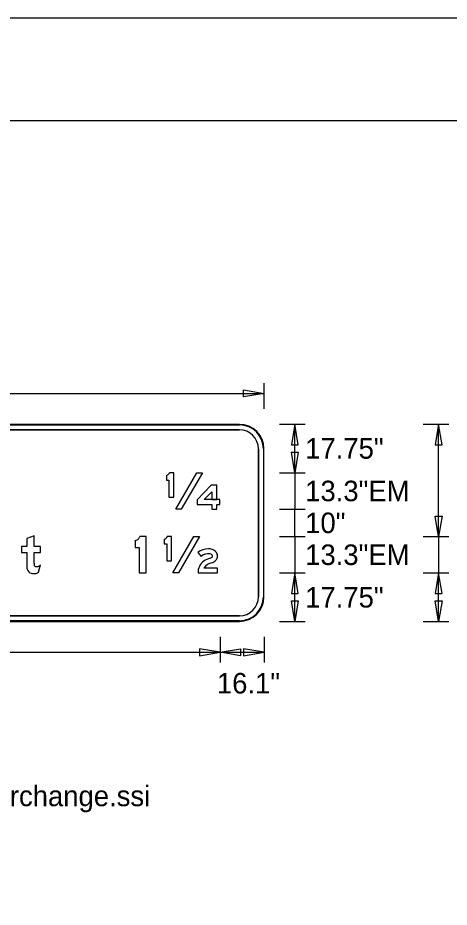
# Model space of a CAD drawing. Extents: x 1806251 to 1809821, y 414895 to 422886.
# Drawn here: x 1809677.776 to 1809679.352, y 414950.976 to 414954.226 of the extents above; entities that cross this region are included whole.
import ezdxf

# ---------------------------------------------------------------- set-up
doc = ezdxf.new("R2010")
doc.units = 0
for name, color, linetype in [('GSBWFILL', 7, 'Continuous'), ('GSCOLORFILL', 7, 'Continuous'), ('GSDIMS', 7, 'Continuous'), ('GSOUTLINE', 7, 'Continuous'), ('GSSHT', 7, 'Continuous')]:
    doc.layers.add(name, color=color, linetype=linetype)

msp = doc.modelspace()

# ---------------------------------------------------------------- linework, layer by layer
at = {"layer": 'GSBWFILL'}
for p, q in [((1809678.5855, 414952.7405), (1809676.6055, 414952.7405)), ((1809676.6055, 414952.7205), (1809678.5855, 414952.7205)), ((1809678.6555, 414952.6505), (1809678.6555, 414952.1105)), ((1809678.6755, 414952.1105), (1809678.6755, 414952.6505)), ((1809678.4342, 414952.2717), (1809678.4458, 414952.2581)), ((1809677.8523, 414952.2), (1809677.8593, 414952.2275)), ((1809678.5855, 414952.0405), (1809676.6057, 414952.0405)), ((1809676.6057, 414952.0205), (1809678.5855, 414952.0205))]:
    msp.add_line(p, q, dxfattribs=at)
for points in [[(1809678.3194, 414952.5536), (1809678.3194, 414952.5367), (1809678.3285, 414952.5367), (1809678.3285, 414952.4748), (1809678.346, 414952.4748), (1809678.346, 414952.5635), (1809678.3306, 414952.5635)], [(1809677.8354, 414952.2327), (1809677.8354, 414952.2716), (1809677.8593, 414952.2716), (1809677.8593, 414952.2946), (1809677.8354, 414952.2946), (1809677.8354, 414952.3328), (1809677.8088, 414952.3227), (1809677.8088, 414952.2946), (1809677.7902, 414952.2946), (1809677.7902, 414952.2716), (1809677.8088, 414952.2716), (1809677.8088, 414952.2247)], [(1809678.2053, 414952.3157), (1809678.2053, 414952.2903), (1809678.219, 414952.2903), (1809678.219, 414952.1975), (1809678.2452, 414952.1975), (1809678.2452, 414952.3305), (1809678.2221, 414952.3305)], [(1809678.3112, 414952.3206), (1809678.3112, 414952.3037), (1809678.3203, 414952.3037), (1809678.3203, 414952.2418), (1809678.3378, 414952.2418), (1809678.3378, 414952.3305), (1809678.3224, 414952.3305)], [(1809678.4345, 414952.1975), (1809678.506, 414952.1975), (1809678.506, 414952.215), (1809678.4562, 414952.215)]]:
    msp.add_lwpolyline(points, dxfattribs=at)
for points in [[(1809678.4299, 414952.5635), (1809678.4504, 414952.5635), (1809678.3736, 414952.4305), (1809678.3531, 414952.4305)], [(1809678.4847, 414952.4305), (1809678.5029, 414952.4305), (1809678.5029, 414952.4479), (1809678.5142, 414952.4479), (1809678.5142, 414952.4658), (1809678.4569, 414952.4658), (1809678.4569, 414952.4658), (1809678.4847, 414952.4943), (1809678.4847, 414952.4658), (1809678.5029, 414952.4658), (1809678.5029, 414952.5179), (1809678.4847, 414952.5179), (1809678.4826, 414952.5179), (1809678.4826, 414952.5179), (1809678.4313, 414952.465), (1809678.4313, 414952.4479), (1809678.4847, 414952.4479)], [(1809678.4193, 414952.3305), (1809678.4398, 414952.3305), (1809678.3631, 414952.1975), (1809678.3426, 414952.1975)]]:
    msp.add_lwpolyline(points, close=True, dxfattribs=at)
for centre, radius, start, end in [((1809678.5855, 414952.6505), 0.09, 0, 90), ((1809678.5855, 414952.6505), 0.07, 0, 90), ((1809678.3158, 414952.5691), 0.0158, 316.0835, 327.7887), ((1809678.3158, 414952.5691), 0.0158, 327.7887, 339.494), ((1809678.3158, 414952.5691), 0.0158, 283.2584, 299.6709), ((1809678.3158, 414952.5691), 0.0158, 299.6709, 316.0835), ((1809677.8604, 414952.2247), 0.0516, 180, 194.8913), ((1809677.8314, 414952.217), 0.0216, 194.8913, 254.4117), ((1809678.0019, 414952.2327), 0.1665, 180, 182.0173), ((1809677.843, 414952.2282), 0.00765, 189.7434, 227.9584), ((1809677.8433, 414952.2284), 0.00801, 227.9584, 270), ((1809677.8433, 414952.2624), 0.042, 270, 279.6927), ((1809677.8486, 414952.2309), 0.00997, 279.6927, 305.2189), ((1809677.8418, 414952.2406), 0.0218, 305.2189, 323.2877), ((1809677.8354, 414952.2313), 0.0364, 254.4117, 270), ((1809677.8354, 414952.2473), 0.0525, 270, 273.675), ((1809677.8373, 414952.2165), 0.0216, 273.675, 286.3959), ((1809677.8345, 414952.2261), 0.0316, 286.3959, 304.22), ((1809678.5855, 414952.1105), 0.09, 270, 0), ((1809678.5855, 414952.1105), 0.07, 270, 0)]:
    msp.add_arc(centre, radius, start, end, dxfattribs=at)
for centre, major_axis, ratio, start_param, end_param in [((1809678.1999, 414952.3388), (0, 0.0238), 0.999985, 3.372996, 3.659448), ((1809678.1999, 414952.3388), (0, 0.0238), 0.999985, 3.659448, 3.945901), ((1809678.1999, 414952.3388), (0, 0.0238), 0.999985, 3.945901, 4.150196), ((1809678.1999, 414952.3388), (0, 0.0238), 0.999985, 4.150196, 4.354491), ((1809678.3076, 414952.3361), (0, 0.0158), 0.999478, 3.372996, 3.659448), ((1809678.3076, 414952.3361), (0, 0.0158), 0.999478, 3.659448, 3.945901), ((1809678.3076, 414952.3361), (0, 0.0158), 0.999478, 3.945901, 4.150196), ((1809678.3076, 414952.3361), (0, 0.0158), 0.999478, 4.150196, 4.354491), ((1809678.4707, 414952.23), (0, 0.0555), 0.999478, 6.248407, 7.003021), ((1809678.4709, 414952.2304), (0, 0.0374), 0.999478, 6.094132, 7.020883), ((1809678.4741, 414952.2489), (0, 0.0366), 0.999478, 5.550079, 6.322931), ((1809678.4756, 414952.2517), (0, 0.0156), 0.999478, 5.490532, 6.129979), ((1809678.4815, 414952.2582), (0, 0.0247), 0.999478, 4.806893, 5.518533), ((1809678.4851, 414952.1993), (0, 0.0506), 0.999478, 0.626572, 1.605438), ((1809678.495, 414952.1855), (0, 0.0676), 0.999478, 0.230695, 0.626088), ((1809678.4928, 414952.1917), (0, 0.0434), 0.999478, 0.176082, 1.00426), ((1809678.4761, 414952.2641), (0, 0.0132), 0.999478, 3.400739, 4.168985), ((1809678.4762, 414952.264), (0, 0.0309), 0.999478, 3.438365, 3.951913), ((1809678.4838, 414952.2595), (0, 0.0043), 0.999478, 4.157725, 5.534803), ((1809678.4816, 414952.2603), (0, 0.0244), 0.999478, 3.907466, 4.724085)]:
    msp.add_ellipse(centre, major_axis=major_axis, ratio=ratio, start_param=start_param, end_param=end_param, dxfattribs=at)
at = {"layer": 'GSCOLORFILL'}
for p, q in [((1809678.5855, 414952.7405), (1809676.6055, 414952.7405)), ((1809678.5855, 414952.7405), (1809676.6055, 414952.7405)), ((1809678.5855, 414952.7405), (1809676.6055, 414952.7405)), ((1809676.6055, 414952.7385), (1809678.5855, 414952.7385)), ((1809676.6055, 414952.7205), (1809678.5855, 414952.7205)), ((1809678.6555, 414952.6505), (1809678.6555, 414952.1105)), ((1809678.6735, 414952.6505), (1809678.6735, 414952.1105)), ((1809678.6755, 414952.1105), (1809678.6755, 414952.6505)), ((1809678.6755, 414952.1105), (1809678.6755, 414952.6505)), ((1809678.6755, 414952.1105), (1809678.6755, 414952.6505)), ((1809678.4342, 414952.2717), (1809678.4458, 414952.2581)), ((1809677.8523, 414952.2), (1809677.8593, 414952.2275)), ((1809678.5855, 414952.0405), (1809676.6057, 414952.0405)), ((1809678.5855, 414952.0225), (1809676.6055, 414952.0225)), ((1809676.6055, 414952.0205), (1809678.5855, 414952.0205)), ((1809676.6055, 414952.0205), (1809678.5855, 414952.0205)), ((1809676.6057, 414952.0205), (1809678.5855, 414952.0205))]:
    msp.add_line(p, q, dxfattribs=at)
for points in [[(1809678.3194, 414952.5536), (1809678.3194, 414952.5367), (1809678.3285, 414952.5367), (1809678.3285, 414952.4748), (1809678.346, 414952.4748), (1809678.346, 414952.5635), (1809678.3306, 414952.5635)], [(1809677.8354, 414952.2327), (1809677.8354, 414952.2716), (1809677.8593, 414952.2716), (1809677.8593, 414952.2946), (1809677.8354, 414952.2946), (1809677.8354, 414952.3328), (1809677.8088, 414952.3227), (1809677.8088, 414952.2946), (1809677.7902, 414952.2946), (1809677.7902, 414952.2716), (1809677.8088, 414952.2716), (1809677.8088, 414952.2247)], [(1809678.2053, 414952.3157), (1809678.2053, 414952.2903), (1809678.219, 414952.2903), (1809678.219, 414952.1975), (1809678.2452, 414952.1975), (1809678.2452, 414952.3305), (1809678.2221, 414952.3305)], [(1809678.3112, 414952.3206), (1809678.3112, 414952.3037), (1809678.3203, 414952.3037), (1809678.3203, 414952.2418), (1809678.3378, 414952.2418), (1809678.3378, 414952.3305), (1809678.3224, 414952.3305)], [(1809678.4345, 414952.1975), (1809678.506, 414952.1975), (1809678.506, 414952.215), (1809678.4562, 414952.215)]]:
    msp.add_lwpolyline(points, dxfattribs=at)
for points in [[(1809678.4299, 414952.5635), (1809678.4504, 414952.5635), (1809678.3736, 414952.4305), (1809678.3531, 414952.4305)], [(1809678.4847, 414952.4305), (1809678.5029, 414952.4305), (1809678.5029, 414952.4479), (1809678.5142, 414952.4479), (1809678.5142, 414952.4658), (1809678.4569, 414952.4658), (1809678.4569, 414952.4658), (1809678.4847, 414952.4943), (1809678.4847, 414952.4658), (1809678.5029, 414952.4658), (1809678.5029, 414952.5179), (1809678.4847, 414952.5179), (1809678.4826, 414952.5179), (1809678.4826, 414952.5179), (1809678.4313, 414952.465), (1809678.4313, 414952.4479), (1809678.4847, 414952.4479)], [(1809678.4193, 414952.3305), (1809678.4398, 414952.3305), (1809678.3631, 414952.1975), (1809678.3426, 414952.1975)]]:
    msp.add_lwpolyline(points, close=True, dxfattribs=at)
for centre, radius, start, end in [((1809678.5855, 414952.6505), 0.09, 0, 90), ((1809678.5855, 414952.6505), 0.09, 0, 90), ((1809678.5855, 414952.6505), 0.09, 0, 90), ((1809678.5855, 414952.6505), 0.088, 0, 90), ((1809678.5855, 414952.6505), 0.07, 0, 90), ((1809678.3158, 414952.5691), 0.0158, 316.0835, 327.7887), ((1809678.3158, 414952.5691), 0.0158, 327.7887, 339.494), ((1809678.3158, 414952.5691), 0.0158, 283.2584, 299.6709), ((1809678.3158, 414952.5691), 0.0158, 299.6709, 316.0835), ((1809677.8604, 414952.2247), 0.0516, 180, 194.8913), ((1809677.8314, 414952.217), 0.0216, 194.8913, 254.4117), ((1809678.0019, 414952.2327), 0.1665, 180, 182.0173), ((1809677.843, 414952.2282), 0.00765, 189.7434, 227.9584), ((1809677.8433, 414952.2284), 0.00801, 227.9584, 270), ((1809677.8433, 414952.2624), 0.042, 270, 279.6927), ((1809677.8486, 414952.2309), 0.00997, 279.6927, 305.2189), ((1809677.8418, 414952.2406), 0.0218, 305.2189, 323.2877), ((1809677.8354, 414952.2313), 0.0364, 254.4117, 270), ((1809677.8354, 414952.2473), 0.0525, 270, 273.675), ((1809677.8373, 414952.2165), 0.0216, 273.675, 286.3959), ((1809677.8345, 414952.2261), 0.0316, 286.3959, 304.22), ((1809678.5855, 414952.1105), 0.09, 270, 0), ((1809678.5855, 414952.1105), 0.09, 270, 0), ((1809678.5855, 414952.1105), 0.07, 270, 0), ((1809678.5855, 414952.1105), 0.09, 270, 0), ((1809678.5855, 414952.1105), 0.088, 270, 0)]:
    msp.add_arc(centre, radius, start, end, dxfattribs=at)
for centre, major_axis, ratio, start_param, end_param in [((1809678.1999, 414952.3388), (0, 0.0238), 0.999985, 3.372996, 3.659448), ((1809678.1999, 414952.3388), (0, 0.0238), 0.999985, 3.659448, 3.945901), ((1809678.1999, 414952.3388), (0, 0.0238), 0.999985, 3.945901, 4.150196), ((1809678.1999, 414952.3388), (0, 0.0238), 0.999985, 4.150196, 4.354491), ((1809678.3076, 414952.3361), (0, 0.0158), 0.999478, 3.372996, 3.659448), ((1809678.3076, 414952.3361), (0, 0.0158), 0.999478, 3.659448, 3.945901), ((1809678.3076, 414952.3361), (0, 0.0158), 0.999478, 3.945901, 4.150196), ((1809678.3076, 414952.3361), (0, 0.0158), 0.999478, 4.150196, 4.354491), ((1809678.4707, 414952.23), (0, 0.0555), 0.999478, 6.248407, 7.003021), ((1809678.4709, 414952.2304), (0, 0.0374), 0.999478, 6.094132, 7.020883), ((1809678.4741, 414952.2489), (0, 0.0366), 0.999478, 5.550079, 6.322931), ((1809678.4756, 414952.2517), (0, 0.0156), 0.999478, 5.490532, 6.129979), ((1809678.4815, 414952.2582), (0, 0.0247), 0.999478, 4.806893, 5.518533), ((1809678.4851, 414952.1993), (0, 0.0506), 0.999478, 0.626572, 1.605438), ((1809678.495, 414952.1855), (0, 0.0676), 0.999478, 0.230695, 0.626088), ((1809678.4928, 414952.1917), (0, 0.0434), 0.999478, 0.176082, 1.00426), ((1809678.4761, 414952.2641), (0, 0.0132), 0.999478, 3.400739, 4.168985), ((1809678.4762, 414952.264), (0, 0.0309), 0.999478, 3.438365, 3.951913), ((1809678.4838, 414952.2595), (0, 0.0043), 0.999478, 4.157725, 5.534803), ((1809678.4816, 414952.2603), (0, 0.0244), 0.999478, 3.907466, 4.724085)]:
    msp.add_ellipse(centre, major_axis=major_axis, ratio=ratio, start_param=start_param, end_param=end_param, dxfattribs=at)
at = {"layer": 'GSDIMS'}
for p, q in [((1809678.676, 414952.7973), (1809678.676, 414952.891)), ((1809676.515, 414952.8535), (1809678.676, 414952.8535)), ((1809678.7323, 414952.741), (1809678.826, 414952.741)), ((1809678.7885, 414952.5635), (1809678.7885, 414952.741)), ((1809679.2573, 414952.741), (1809679.351, 414952.741)), ((1809679.3135, 414952.3305), (1809679.3135, 414952.741)), ((1809678.7323, 414952.5635), (1809678.826, 414952.5635)), ((1809678.7323, 414952.5635), (1809678.826, 414952.5635)), ((1809678.7885, 414952.5635), (1809678.7885, 414952.4305)), ((1809678.7323, 414952.4305), (1809678.826, 414952.4305)), ((1809678.7323, 414952.4305), (1809678.826, 414952.4305)), ((1809678.7885, 414952.3305), (1809678.7885, 414952.4305)), ((1809678.7323, 414952.3305), (1809678.826, 414952.3305)), ((1809678.7323, 414952.3305), (1809678.826, 414952.3305)), ((1809678.7885, 414952.3305), (1809678.7885, 414952.1975)), ((1809679.2573, 414952.3305), (1809679.351, 414952.3305)), ((1809679.2573, 414952.3305), (1809679.351, 414952.3305)), ((1809679.3135, 414952.3305), (1809679.3135, 414952.1975)), ((1809678.7323, 414952.1975), (1809678.826, 414952.1975)), ((1809678.7323, 414952.1975), (1809678.826, 414952.1975)), ((1809678.7885, 414952.02), (1809678.7885, 414952.1975)), ((1809679.2573, 414952.1975), (1809679.351, 414952.1975)), ((1809679.2573, 414952.1975), (1809679.351, 414952.1975)), ((1809679.3135, 414952.02), (1809679.3135, 414952.1975)), ((1809678.7323, 414952.02), (1809678.826, 414952.02)), ((1809679.2573, 414952.02), (1809679.351, 414952.02)), ((1809678.515, 414951.9637), (1809678.515, 414951.87)), ((1809678.515, 414951.9637), (1809678.515, 414951.87)), ((1809678.676, 414951.9637), (1809678.676, 414951.87)), ((1809676.6764, 414951.9075), (1809678.515, 414951.9075)), ((1809678.515, 414951.9075), (1809678.676, 414951.9075))]:
    msp.add_line(p, q, dxfattribs=at)
for points in [[(1809678.676, 414952.8535), (1809678.601, 414952.841), (1809678.601, 414952.866)], [(1809678.7885, 414952.741), (1809678.776, 414952.666), (1809678.801, 414952.666)], [(1809679.3135, 414952.741), (1809679.301, 414952.666), (1809679.326, 414952.666)], [(1809678.7885, 414952.5635), (1809678.776, 414952.6385), (1809678.801, 414952.6385)], [(1809679.3135, 414952.3305), (1809679.301, 414952.4055), (1809679.326, 414952.4055)], [(1809678.7885, 414952.1975), (1809678.776, 414952.1225), (1809678.801, 414952.1225)], [(1809679.3135, 414952.1975), (1809679.301, 414952.1225), (1809679.326, 414952.1225)], [(1809678.7885, 414952.02), (1809678.776, 414952.095), (1809678.801, 414952.095)], [(1809679.3135, 414952.02), (1809679.301, 414952.095), (1809679.326, 414952.095)], [(1809678.515, 414951.9075), (1809678.44, 414951.92), (1809678.44, 414951.895)], [(1809678.515, 414951.9075), (1809678.59, 414951.92), (1809678.59, 414951.895)], [(1809678.676, 414951.9075), (1809678.601, 414951.92), (1809678.601, 414951.895)]]:
    msp.add_lwpolyline(points, close=True, dxfattribs=at)
at = {"layer": 'GSOUTLINE'}
for p, q in [((1809678.5855, 414952.7405), (1809676.6055, 414952.7405)), ((1809678.5855, 414952.7205), (1809676.6055, 414952.7205)), ((1809678.6555, 414952.1105), (1809678.6555, 414952.6505)), ((1809678.6755, 414952.1105), (1809678.6755, 414952.6505)), ((1809678.4342, 414952.2717), (1809678.4458, 414952.2581)), ((1809677.8523, 414952.2), (1809677.8593, 414952.2275)), ((1809676.6055, 414952.0405), (1809678.5855, 414952.0405)), ((1809676.6055, 414952.0205), (1809678.5855, 414952.0205))]:
    msp.add_line(p, q, dxfattribs=at)
for points in [[(1809678.3194, 414952.5536), (1809678.3194, 414952.5367), (1809678.3285, 414952.5367), (1809678.3285, 414952.4748), (1809678.346, 414952.4748), (1809678.346, 414952.5635), (1809678.3306, 414952.5635)], [(1809677.8354, 414952.2327), (1809677.8354, 414952.2716), (1809677.8593, 414952.2716), (1809677.8593, 414952.2946), (1809677.8354, 414952.2946), (1809677.8354, 414952.3328), (1809677.8088, 414952.3227), (1809677.8088, 414952.2946), (1809677.7902, 414952.2946), (1809677.7902, 414952.2716), (1809677.8088, 414952.2716), (1809677.8088, 414952.2247)], [(1809678.2053, 414952.3157), (1809678.2053, 414952.2903), (1809678.219, 414952.2903), (1809678.219, 414952.1975), (1809678.2452, 414952.1975), (1809678.2452, 414952.3305), (1809678.2221, 414952.3305)], [(1809678.3112, 414952.3206), (1809678.3112, 414952.3037), (1809678.3203, 414952.3037), (1809678.3203, 414952.2418), (1809678.3378, 414952.2418), (1809678.3378, 414952.3305), (1809678.3224, 414952.3305)], [(1809678.4345, 414952.1975), (1809678.506, 414952.1975), (1809678.506, 414952.215), (1809678.4562, 414952.215)]]:
    msp.add_lwpolyline(points, dxfattribs=at)
for points in [[(1809678.4299, 414952.5635), (1809678.4504, 414952.5635), (1809678.3736, 414952.4305), (1809678.3531, 414952.4305)], [(1809678.5029, 414952.4305), (1809678.5029, 414952.4479), (1809678.5142, 414952.4479), (1809678.5142, 414952.4658), (1809678.5029, 414952.4658), (1809678.5029, 414952.5179), (1809678.4847, 414952.5179), (1809678.4826, 414952.5179), (1809678.4826, 414952.5179), (1809678.4313, 414952.465), (1809678.4313, 414952.4479), (1809678.4847, 414952.4479), (1809678.4847, 414952.4305)], [(1809678.4847, 414952.4943), (1809678.4847, 414952.4658), (1809678.4569, 414952.4658)], [(1809678.4193, 414952.3305), (1809678.4398, 414952.3305), (1809678.3631, 414952.1975), (1809678.3426, 414952.1975)]]:
    msp.add_lwpolyline(points, close=True, dxfattribs=at)
for centre, radius, start, end in [((1809678.5855, 414952.6505), 0.09, 0, 90), ((1809678.5855, 414952.6505), 0.07, 0, 90), ((1809678.3158, 414952.5691), 0.0158, 316.0835, 327.7887), ((1809678.3158, 414952.5691), 0.0158, 327.7887, 339.494), ((1809678.3158, 414952.5691), 0.0158, 283.2584, 299.6709), ((1809678.3158, 414952.5691), 0.0158, 299.6709, 316.0835), ((1809677.8604, 414952.2247), 0.0516, 180, 194.8913), ((1809677.8314, 414952.217), 0.0216, 194.8913, 254.4117), ((1809678.0019, 414952.2327), 0.1665, 180, 182.0173), ((1809677.843, 414952.2282), 0.00765, 189.7434, 227.9584), ((1809677.8433, 414952.2284), 0.00801, 227.9584, 270), ((1809677.8433, 414952.2624), 0.042, 270, 279.6927), ((1809677.8486, 414952.2309), 0.00997, 279.6927, 305.2189), ((1809677.8418, 414952.2406), 0.0218, 305.2189, 323.2877), ((1809677.8354, 414952.2313), 0.0364, 254.4117, 270), ((1809677.8354, 414952.2473), 0.0525, 270, 273.675), ((1809677.8373, 414952.2165), 0.0216, 273.675, 286.3959), ((1809677.8345, 414952.2261), 0.0316, 286.3959, 304.22), ((1809678.5855, 414952.1105), 0.09, 270, 0), ((1809678.5855, 414952.1105), 0.07, 270, 0)]:
    msp.add_arc(centre, radius, start, end, dxfattribs=at)
for centre, major_axis, ratio, start_param, end_param in [((1809678.1999, 414952.3388), (0, 0.0238), 0.999985, 3.372996, 3.659448), ((1809678.1999, 414952.3388), (0, 0.0238), 0.999985, 3.659448, 3.945901), ((1809678.1999, 414952.3388), (0, 0.0238), 0.999985, 3.945901, 4.150196), ((1809678.1999, 414952.3388), (0, 0.0238), 0.999985, 4.150196, 4.354491), ((1809678.3076, 414952.3361), (0, 0.0158), 0.999478, 3.372996, 3.659448), ((1809678.3076, 414952.3361), (0, 0.0158), 0.999478, 3.659448, 3.945901), ((1809678.3076, 414952.3361), (0, 0.0158), 0.999478, 3.945901, 4.150196), ((1809678.3076, 414952.3361), (0, 0.0158), 0.999478, 4.150196, 4.354491), ((1809678.4707, 414952.23), (0, 0.0555), 0.999478, 6.248407, 7.003021), ((1809678.4709, 414952.2304), (0, 0.0374), 0.999478, 6.094132, 7.020883), ((1809678.4741, 414952.2489), (0, 0.0366), 0.999478, 5.550079, 6.322931), ((1809678.4756, 414952.2517), (0, 0.0156), 0.999478, 5.490532, 6.129979), ((1809678.4815, 414952.2582), (0, 0.0247), 0.999478, 4.806893, 5.518533), ((1809678.4851, 414952.1993), (0, 0.0506), 0.999478, 0.626572, 1.605438), ((1809678.495, 414952.1855), (0, 0.0676), 0.999478, 0.230695, 0.626088), ((1809678.4928, 414952.1917), (0, 0.0434), 0.999478, 0.176082, 1.00426), ((1809678.4761, 414952.2641), (0, 0.0132), 0.999478, 3.400739, 4.168985), ((1809678.4762, 414952.264), (0, 0.0309), 0.999478, 3.438365, 3.951913), ((1809678.4838, 414952.2595), (0, 0.0043), 0.999478, 4.157725, 5.534803), ((1809678.4816, 414952.2603), (0, 0.0244), 0.999478, 3.907466, 4.724085)]:
    msp.add_ellipse(centre, major_axis=major_axis, ratio=ratio, start_param=start_param, end_param=end_param, dxfattribs=at)
at = {"layer": 'GSSHT'}
msp.add_line((1809672.1353, 414954.2262), (1809684.8895, 414954.2262), dxfattribs=at)
msp.add_lwpolyline([(1809672.6344, 414953.8511), (1809684.6385, 414953.8511), (1809684.6385, 414946.3474), (1809672.6344, 414946.3474)], close=True, dxfattribs=at)

# ---------------------------------------------------------------- texts
at = {"layer": 'GSDIMS'}
for s, p in [('17.75"', (1809678.826, 414952.615)), ('13.3"EM', (1809678.826, 414952.4595)), ('10"', (1809678.826, 414952.343)), ('13.3"EM', (1809678.826, 414952.2265)), ('17.75"', (1809678.826, 414952.071)), ('16.1"', (1809678.5035, 414951.757)), ('Panel Style: guide_fwy_interchange.ssi', (1809676.515, 414951.345))]:
    msp.add_text(s, height=0.075, dxfattribs=at).set_placement(p)

doc.saveas('drawing.dxf')
